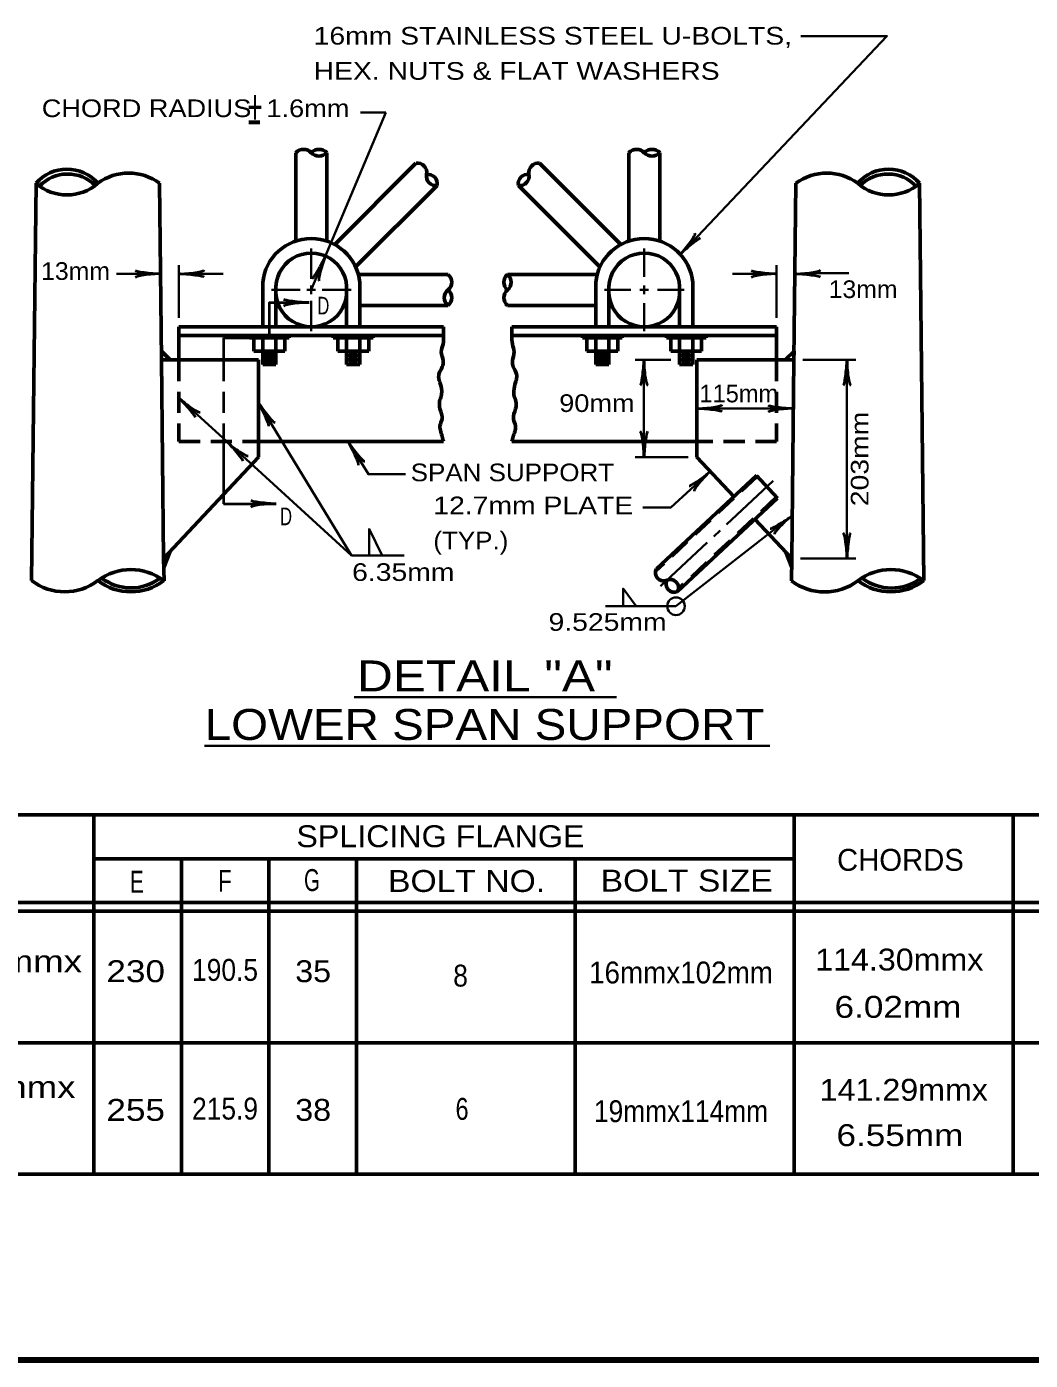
# Model space of a CAD drawing. Extents: x -29 to 827, y -14 to 530.
# Drawn here: x 320.1 to 457.6, y -2.8 to 179.9 of the extents above; entities that cross this region are included whole.
import ezdxf
from ezdxf.enums import TextEntityAlignment as Align

# ---------------------------------------------------------------- set-up
doc = ezdxf.new("R2010")
doc.units = 0
doc.header["$LTSCALE"] = 0.97
doc.linetypes.add('MEDIUM_DASHED', pattern=[4.5, 3, -1.5])
doc.layers.add('1', color=7, linetype='Continuous', lineweight=53)

msp = doc.modelspace()

# ---------------------------------------------------------------- linework, layer by layer
at = {"layer": '1', "lineweight": 35}
for p, q in [((359.0691, 143.7902), (369.2931, 168.1022)), ((369.2931, 168.1022), (365.8112, 168.1022)), ((359.0691, 149.4542), (359.0691, 145.3022)), ((404.7171, 149.4542), (404.7171, 145.5902)), ((340.9251, 139.9502), (340.9251, 147.1982)), ((422.8611, 139.9502), (422.8611, 147.1982)), ((338.4051, 145.9982), (332.3571, 145.9982)), ((340.9251, 145.9982), (346.9731, 145.9982)), ((359.0691, 144.3902), (359.0691, 143.1902)), ((404.7171, 144.3902), (404.7171, 143.1902)), ((422.8611, 145.9982), (416.8131, 145.9982)), ((426.7244, 146.0687), (432.7724, 146.0687)), ((353.6211, 143.7902), (357.5571, 143.7902)), ((360.5811, 143.7902), (364.5171, 143.7902)), ((402.8931, 143.7902), (399.2691, 143.7902)), ((405.3171, 143.7902), (404.1171, 143.7902)), ((410.1651, 143.7902), (406.5171, 143.7902)), ((359.0691, 142.2782), (359.0691, 138.1262)), ((404.7171, 141.9662), (404.7171, 138.1262)), ((408.3411, 134.2142), (403.4691, 134.2142)), ((404.6691, 134.2142), (404.6691, 120.8942)), ((426.4371, 134.2142), (433.7091, 134.2142)), ((432.4851, 134.2142), (432.4851, 106.9982)), ((340.9251, 129.0062), (347.4989, 123.0062)), ((364.5651, 107.4302), (351.8451, 128.3342)), ((411.9411, 127.5422), (425.1651, 127.5422)), ((347.4991, 123.0062), (364.5651, 107.4302)), ((410.7171, 120.8942), (403.4691, 120.8942)), ((422.4051, 117.6542), (415.9971, 111.6782)), ((409.0611, 100.4702), (424.9971, 112.8782)), ((415.1091, 110.8382), (414.2451, 110.0222)), ((413.3571, 109.2062), (406.9491, 103.2062)), ((364.5651, 107.4302), (371.8131, 107.4302)), ((426.1491, 106.9982), (433.7091, 106.9982)), ((409.0611, 100.4702), (399.3891, 100.4702)), ((364.9491, 87.9806), (400.9011, 87.9806)), ((344.4291, 81.3326), (421.9251, 81.3326))]:
    msp.add_line(p, q, dxfattribs=at)
at = {"layer": '1'}
for p, q in [((356.9571, 162.5822), (356.9571, 150.4862)), ((361.1811, 162.5822), (361.1811, 150.4862)), ((362.2851, 150.0062), (373.4211, 161.1662)), ((401.5011, 150.0062), (390.3411, 161.1662)), ((402.6051, 162.5822), (402.6051, 150.4862)), ((406.8291, 162.5822), (406.8291, 150.4862)), ((321.3411, 158.4062), (320.7411, 103.9742)), ((338.2851, 158.4062), (338.5491, 134.2142)), ((365.1411, 146.9342), (376.3251, 158.0942)), ((398.6211, 146.9342), (387.4611, 158.0942)), ((425.5011, 158.4062), (425.2371, 134.2142)), ((442.4451, 158.4062), (443.0451, 103.9742)), ((352.4211, 144.7982), (352.4211, 138.7502)), ((365.5251, 145.9022), (377.8131, 145.9022)), ((365.7171, 144.7982), (365.7171, 138.7502)), ((398.2611, 145.9022), (385.9731, 145.9022)), ((398.0691, 144.7982), (398.0691, 138.7502)), ((411.3651, 144.7982), (411.3651, 138.7502)), ((354.2211, 143.5742), (354.2211, 138.7502)), ((363.9171, 143.5742), (363.9171, 138.7502)), ((399.8691, 143.5742), (399.8691, 138.7502)), ((409.5411, 143.5742), (409.5411, 138.7502)), ((365.7171, 141.6782), (377.8131, 141.6782)), ((398.0691, 141.6782), (385.9731, 141.6782)), ((340.9251, 138.7502), (377.2131, 138.7502)), ((340.9251, 138.7502), (340.9251, 134.2142)), ((340.9251, 137.5262), (377.2131, 137.5262)), ((350.5971, 137.5262), (350.5971, 137.2382)), ((350.5971, 137.2382), (356.0451, 137.2382)), ((351.1971, 137.2382), (351.1971, 135.4142)), ((352.4211, 137.2382), (352.4211, 133.5902)), ((354.2211, 137.2382), (354.2211, 133.5902)), ((355.4451, 137.2382), (355.4451, 135.4142)), ((356.0451, 137.5262), (356.0451, 137.2382)), ((362.0931, 137.5262), (362.0931, 137.2382)), ((362.0931, 137.2382), (367.5411, 137.2382)), ((362.6931, 137.2382), (362.6931, 135.4142)), ((363.9171, 137.2382), (363.9171, 133.5902)), ((365.7171, 137.2382), (365.7171, 133.5902)), ((366.9411, 137.2382), (366.9411, 135.4142)), ((367.5411, 137.5262), (367.5411, 137.2382)), ((422.8611, 138.7502), (386.5731, 138.7502)), ((422.8611, 137.5262), (386.5731, 137.5262)), ((396.2451, 137.5262), (396.2451, 137.2382)), ((401.6931, 137.2382), (396.2451, 137.2382)), ((396.8451, 137.2382), (396.8451, 135.4142)), ((398.0691, 137.2382), (398.0691, 133.5902)), ((399.8691, 137.2382), (399.8691, 133.5902)), ((401.0931, 137.2382), (401.0931, 135.4142)), ((401.6931, 137.5262), (401.6931, 137.2382)), ((407.7411, 137.5262), (407.7411, 137.2382)), ((413.1891, 137.2382), (407.7411, 137.2382)), ((408.3411, 137.2382), (408.3411, 135.4142)), ((409.5411, 137.2382), (409.5411, 133.5902)), ((411.3651, 137.2382), (411.3651, 133.5902)), ((412.5651, 137.2382), (412.5651, 135.4142)), ((413.1891, 137.5262), (413.1891, 137.2382)), ((422.8611, 138.7502), (422.8611, 134.2142)), ((351.1971, 135.4142), (355.4451, 135.4142)), ((362.6931, 135.4142), (366.9411, 135.4142)), ((401.0931, 135.4142), (396.8451, 135.4142)), ((412.5651, 135.4142), (408.3411, 135.4142)), ((338.5491, 134.2142), (351.8451, 134.2142)), ((351.8451, 134.2142), (351.8451, 120.8942)), ((352.4211, 134.8142), (354.2211, 134.8142)), ((352.4211, 134.2142), (354.2211, 134.2142)), ((352.4211, 133.5902), (354.2211, 133.5902)), ((352.7091, 135.1022), (353.9331, 135.1022)), ((352.7091, 134.5022), (353.9331, 134.5022)), ((352.7091, 133.9022), (353.9331, 133.9022)), ((363.9171, 134.8142), (365.7171, 134.8142)), ((363.9171, 134.2142), (365.7171, 134.2142)), ((363.9171, 133.5902), (365.7171, 133.5902)), ((364.2051, 135.1022), (365.4291, 135.1022)), ((364.2051, 134.5022), (365.4291, 134.5022)), ((364.2051, 133.9022), (365.4291, 133.9022)), ((399.8691, 134.8142), (398.0691, 134.8142)), ((399.8691, 134.2142), (398.0691, 134.2142)), ((399.8691, 133.5902), (398.0691, 133.5902)), ((399.5811, 135.1022), (398.3571, 135.1022)), ((399.5811, 134.5022), (398.3571, 134.5022)), ((399.5811, 133.9022), (398.3571, 133.9022)), ((411.3651, 134.8142), (409.5411, 134.8142)), ((411.3651, 134.2142), (409.5411, 134.2142)), ((411.3651, 133.5902), (409.5411, 133.5902)), ((411.0531, 135.1022), (409.8531, 135.1022)), ((411.0531, 134.5022), (409.8531, 134.5022)), ((411.0531, 133.9022), (409.8531, 133.9022)), ((411.9411, 134.2142), (411.9411, 120.8942)), ((425.2371, 134.2142), (411.9411, 134.2142)), ((351.8451, 123.0062), (377.2131, 123.0062)), ((411.9411, 123.0062), (386.5731, 123.0062)), ((351.8451, 120.8942), (338.8371, 106.9982)), ((411.9411, 120.8942), (416.9811, 115.4942)), ((420.0771, 118.3742), (406.3731, 105.5822)), ((420.0771, 118.3742), (422.9811, 115.2782)), ((422.9811, 115.2782), (409.2771, 102.4862)), ((419.8851, 112.3982), (424.9251, 106.9982)), ((338.8371, 106.9982), (338.8851, 103.9502)), ((424.9251, 106.9982), (424.9011, 103.9502)), ((329.2642, 71.8697), (329.2642, 22.6697)), ((425.2642, 71.8697), (425.2642, 22.6697)), ((455.2642, 71.8697), (455.2642, 22.6697)), ((329.2642, 65.8697), (425.2642, 65.8697)), ((341.2642, 65.8697), (341.2642, 22.6697)), ((353.2642, 65.8697), (353.2642, 22.6697)), ((365.2642, 65.8697), (365.2642, 22.6697)), ((395.2642, 65.8697), (395.2642, 22.6697)), ((221.2642, 59.8697), (580.4623, 59.8697)), ((221.2642, 58.6697), (580.4623, 58.6697)), ((221.2642, 40.6697), (580.4623, 40.6697)), ((221.2642, 22.6697), (580.4623, 22.6697))]:
    msp.add_line(p, q, dxfattribs=at)
at = {"layer": '1', "lineweight": 40}
for p, q in [((347.0211, 137.2382), (347.0211, 134.2142)), ((347.0211, 123.0062), (347.0211, 114.5102)), ((347.0211, 114.5102), (354.2691, 114.5102))]:
    msp.add_line(p, q, dxfattribs=at)
at = {"layer": '1', "linetype": 'MEDIUM_DASHED', "lineweight": 40}
msp.add_line((347.0211, 134.2142), (347.0211, 123.0062), dxfattribs=at)
at = {"layer": '1', "linetype": 'MEDIUM_DASHED'}
for p, q in [((420.1731, 118.2782), (406.2771, 105.2702)), ((422.8611, 115.3982), (409.3971, 102.7982))]:
    msp.add_line(p, q, dxfattribs=at)
at = {"layer": '1', "lineweight": 158}
msp.add_line((820.0407, -2.8455), (28.4407, -2.8455), dxfattribs=at)
at = {"layer": '1', "lineweight": 35}
for points in [[(409.6611, 148.6622), (437.9736, 178.569), (426.1802, 178.569)], [(358.4691, 143.7902), (359.0691, 143.7902), (359.6691, 143.7902)], [(364.1331, 123.0062), (366.8931, 118.5422), (372.0051, 118.5422)], [(413.7651, 118.9262), (408.3411, 113.9822), (404.5251, 113.9822)], [(366.9891, 107.4302), (366.9891, 111.0542), (368.7891, 107.4302)], [(401.8131, 100.4702), (401.8131, 102.8702), (403.6131, 100.4702)]]:
    msp.add_lwpolyline(points, dxfattribs=at)
at = {"layer": '1', "lineweight": 40}
msp.add_lwpolyline([(347.0211, 137.2382), (353.3331, 137.2382), (353.3331, 142.0622), (358.7571, 142.0622)], dxfattribs=at)
at = {"layer": '1'}
for points in [[(338.5251, 135.4142), (339.7491, 134.2142), (338.5491, 134.2142)], [(425.2611, 135.4142), (424.0371, 134.2142), (425.2371, 134.2142)]]:
    msp.add_lwpolyline(points, close=True, dxfattribs=at)
for points in [[(338.5491, 134.2142), (338.8371, 106.9982), (339.6771, 107.8622), (338.8611, 105.7742), (338.8371, 106.9982)], [(425.2371, 134.2142), (424.9251, 106.9982), (424.1091, 107.8622), (424.9251, 105.7742), (424.9251, 106.9982)], [(221.2642, 71.8697), (329.2642, 71.8697), (425.2642, 71.8697), (580.4623, 71.8697)]]:
    msp.add_lwpolyline(points, dxfattribs=at)
at = {"layer": '1', "linetype": 'MEDIUM_DASHED'}
for points in [[(340.9251, 134.2142), (340.9251, 123.0062), (351.8451, 123.0062)], [(422.8611, 134.2142), (422.8611, 123.0062), (411.9411, 123.0062)]]:
    msp.add_lwpolyline(points, dxfattribs=at)
at = {"layer": '1', "lineweight": 35}
msp.add_circle((409.0627, 100.4608), 1.2096, dxfattribs=at)
at = {"layer": '1'}
for centre, radius, start, end in [((358.0087, 161.5878), 1.4582, 43.46312, 136.53688), ((360.1255, 161.5878), 1.4582, 43.46312, 136.53688), ((403.6554, 161.5878), 1.4582, 43.46312, 136.53688), ((405.7722, 161.5888), 1.4582, 43.46312, 136.53688), ((360.1255, 163.593), 1.4582, 223.46312, 316.53687), ((373.5949, 159.865), 1.3009, 349.34003, 97.33783), ((390.186, 159.865), 1.3009, 82.66217, 190.65997), ((405.7722, 163.594), 1.4582, 223.46312, 316.53687), ((325.5748, 154.759), 5.5813, 40.66498, 139.33502), ((325.682, 154.2875), 5.3757, 45.34412, 136.03167), ((334.042, 152.7314), 7.0719, 53.22658, 126.77342), ((376.1518, 159.3836), 1.3009, 169.34003, 277.33783), ((375.0395, 158.3342), 1.3009, 349.34003, 97.33783), ((388.7414, 158.3342), 1.3009, 82.66217, 190.65997), ((387.6291, 159.3836), 1.3009, 262.66217, 10.65997), ((429.7389, 152.7314), 7.0719, 53.22658, 126.77342), ((438.2061, 154.759), 5.5813, 40.66498, 139.33502), ((438.0989, 154.2875), 5.3757, 43.96833, 134.65588), ((325.5748, 163.2189), 6.4175, 228.72298, 311.27702), ((438.2061, 163.2189), 6.4175, 228.72298, 311.27702), ((359.0671, 144.1561), 6.6829, 5.43705, 174.56295), ((404.7138, 144.1561), 6.6829, 5.43705, 174.56295), ((359.0671, 143.9893), 4.8557, 355.16125, 184.83875), ((404.7138, 143.9893), 4.8557, 355.16125, 184.83875), ((376.9639, 144.8446), 1.3587, 308.8354, 51.1646), ((386.8154, 144.8446), 1.3587, 128.8354, 231.1646), ((385.1129, 144.8446), 1.3587, 308.8354, 51.1646), ((359.0671, 143.583), 4.8557, 175.16125, 4.83875), ((378.6664, 142.7278), 1.3587, 128.8354, 231.1646), ((376.9639, 142.7278), 1.3587, 308.8354, 51.1646), ((386.817, 142.7278), 1.3587, 128.8354, 231.1646), ((404.7138, 143.583), 4.8557, 175.16125, 4.83875), ((334.3444, 97.9986), 7.4811, 52.67567, 127.32434), ((334.3663, 109.6535), 6.6815, 232.97178, 306.38302), ((407.3634, 105.0468), 1.1159, 151.522, 294.60765), ((438.5081, 97.9984), 7.4811, 52.67567, 127.32434), ((438.6093, 109.6343), 6.6815, 232.97178, 306.38302), ((325.2724, 109.9131), 7.4811, 232.67566, 307.32433), ((334.3444, 109.9131), 7.4811, 232.67566, 307.32433), ((408.809, 103.5002), 1.1159, 151.522, 294.60765), ((408.2928, 103.0177), 1.1159, 331.522, 114.60765), ((429.4361, 109.8966), 7.4811, 232.67566, 307.32433), ((438.5081, 109.9129), 7.4811, 232.67566, 307.32433)]:
    msp.add_arc(centre, radius, start, end, dxfattribs=at)
at = {"layer": '1', "lineweight": 40}
for centre, major_axis, ratio, start_param, end_param in [((410.3169, 149.8469), (-1.3478, -1.6984), 0.122415, 0.89635335, 3.14159265), ((410.7698, 149.4669), (-1.6149, -1.3968), 0.07063, 3.14071475, 5.41810995), ((360.2596, 147.2844), (1.019, 1.8764), 0.07063, 3.14071475, 5.41810995), ((360.8174, 147.0884), (0.6627, 2.0645), 0.122415, 0.89635335, 3.14159265), ((337.0442, 146.2549), (2.1246, -0.2125), 0.07063, 3.14071475, 5.41810995), ((337.0442, 146.2549), (2.1246, -0.2125), 0.07063, 3.14071475, 5.41810995), ((342.243, 146.3331), (-2.16, -0.1889), 0.122415, 0.89635335, 3.14159265), ((342.243, 146.3331), (-2.16, -0.1889), 0.122415, 0.89635335, 3.14159265), ((421.5024, 146.2549), (2.1246, -0.2125), 0.07063, 3.14071475, 5.41810995), ((426.7012, 146.3331), (-2.16, -0.1889), 0.122415, 0.89635335, 3.14159265), ((337.0797, 145.6647), (2.16, 0.1889), 0.122415, 0.89635335, 3.14159265), ((337.0797, 145.6647), (2.16, 0.1889), 0.122415, 0.89635335, 3.14159265), ((342.2785, 145.743), (-2.1246, 0.2125), 0.07063, 3.14071475, 5.41810995), ((342.2785, 145.743), (-2.1246, 0.2125), 0.07063, 3.14071475, 5.41810995), ((421.5379, 145.6647), (2.16, 0.1889), 0.122415, 0.89635335, 3.14159265), ((426.7367, 145.743), (-2.1246, 0.2125), 0.07063, 3.14071475, 5.41810995), ((357.4094, 142.3237), (2.1246, -0.2125), 0.07063, 3.14071475, 5.41810995), ((357.4448, 141.7335), (2.16, 0.1889), 0.122415, 0.89635335, 3.14159265), ((404.4174, 132.8501), (0.2125, 2.1246), 0.07063, 3.14071475, 5.41810995), ((404.4174, 132.8501), (0.2125, 2.1246), 0.07063, 3.14071475, 5.41810995), ((405.0076, 132.8855), (-0.1889, 2.16), 0.122415, 0.89635335, 3.14159265), ((405.0076, 132.8855), (-0.1889, 2.16), 0.122415, 0.89635335, 3.14159265), ((432.2383, 132.8501), (0.2125, 2.1246), 0.07063, 3.14071475, 5.41810995), ((432.2383, 132.8501), (0.2125, 2.1246), 0.07063, 3.14071475, 5.41810995), ((432.8285, 132.8855), (-0.1889, 2.16), 0.122415, 0.89635335, 3.14159265), ((432.8285, 132.8855), (-0.1889, 2.16), 0.122415, 0.89635335, 3.14159265), ((341.7518, 127.9012), (1.4262, -1.5891), 0.07063, 6.28230741, 8.55970261), ((342.1234, 128.361), (-1.7228, 1.3164), 0.122415, 0.89635335, 3.14159265), ((352.3356, 127.0423), (0.9225, -1.9256), 0.07063, 6.28230741, 8.55970261), ((352.3356, 127.0423), (0.9225, -1.9256), 0.07063, 6.28230741, 8.55970261), ((352.8214, 127.3793), (-1.2838, 1.7473), 0.122415, 0.89635335, 3.14159265), ((352.8214, 127.3793), (-1.2838, 1.7473), 0.122415, 0.89635335, 3.14159265), ((413.2509, 127.8868), (-2.16, -0.1889), 0.122415, 0.89635335, 3.14159265), ((413.2509, 127.8868), (-2.16, -0.1889), 0.122415, 0.89635335, 3.14159265), ((423.8073, 127.8086), (2.1246, -0.2125), 0.07063, 3.14071475, 5.41810995), ((413.2863, 127.2967), (-2.1246, 0.2125), 0.07063, 3.14071475, 5.41810995), ((413.2863, 127.2967), (-2.1246, 0.2125), 0.07063, 3.14071475, 5.41810995), ((423.8428, 127.2184), (2.16, 0.1889), 0.122415, 0.89635335, 3.14159265), ((404.3392, 122.2197), (0.1889, -2.16), 0.122415, 0.89635335, 3.14159265), ((404.9293, 122.2552), (-0.2125, -2.1246), 0.07063, 3.14071475, 5.41810995), ((348.3211, 121.9122), (-1.4147, 1.5766), 0.07063, 3.14071475, 5.41810995), ((348.6898, 122.3684), (-1.7091, 1.3061), 0.122415, 0.89635335, 3.14159265), ((364.6271, 121.7104), (0.9383, -1.918), 0.07063, 6.28230741, 8.55970261), ((365.1101, 122.0513), (-1.2981, 1.7367), 0.122415, 0.89635335, 3.14159265), ((412.5918, 118.2119), (-1.7107, -1.2777), 0.07063, 6.28230741, 8.55970261), ((413.0164, 117.8005), (1.4659, 1.5976), 0.122415, 0.89635335, 3.14159265), ((352.9492, 114.1793), (2.16, 0.1889), 0.122415, 0.89635335, 3.14159265), ((352.9138, 114.7695), (2.1246, -0.2125), 0.07063, 3.14071475, 5.41810995), ((423.7729, 112.2434), (1.8067, 1.138), 0.07063, 3.14071475, 5.41810995), ((424.1636, 111.7996), (1.588, 1.4763), 0.122415, 0.89635335, 3.14159265), ((432.1601, 108.3075), (0.1889, -2.16), 0.122415, 0.89635335, 3.14159265), ((432.7502, 108.343), (-0.2125, -2.1246), 0.07063, 3.14071475, 5.41810995)]:
    msp.add_ellipse(centre, major_axis=major_axis, ratio=ratio, start_param=start_param, end_param=end_param, dxfattribs=at)
at = {"layer": '1'}
for points in [[(377.2131, 138.7502), (377.2131, 138.2702), (377.2131, 137.5262), (377.1411, 136.3742), (376.8771, 135.2942), (377.1411, 134.0702), (377.0211, 133.2542), (376.5651, 132.2462), (376.5651, 131.5502), (376.7091, 131.1182), (376.9491, 129.9662), (376.8771, 129.2462), (376.6611, 128.5502), (376.7091, 127.5182), (376.9971, 126.1022), (376.7091, 125.1662), (376.8291, 124.3502), (377.0211, 123.7262), (377.2131, 123.0062)], [(386.5731, 138.7502), (386.5491, 138.2702), (386.5731, 137.5262), (386.6451, 136.3742), (386.8851, 135.2942), (386.6451, 134.0702), (386.7651, 133.2542), (387.1971, 132.2462), (387.1971, 131.5502), (387.0771, 131.1182), (386.8371, 129.9662), (386.8851, 129.2462), (387.1251, 128.5502), (387.0771, 127.5182), (386.7891, 126.1022), (387.0771, 125.1662), (386.9571, 124.3502), (386.7651, 123.7262), (386.5731, 123.0062)]]:
    msp.add_spline(points, degree=3, dxfattribs=at)

# ---------------------------------------------------------------- texts
for s, height, width, p in [('16mm STAINLESS STEEL U-BOLTS,', 2.419, 1.2, (359.3952, 177.4008)), ('HEX. NUTS & FLAT WASHERS', 2.419, 1.2, (359.3952, 172.5816)), ('CHORD RADIUS  1.6mm', 2.419, 1.15, (322.1284, 167.4686)), ('+', 4.8, 0.55, (350.3364, 166.4852)), ('13mm', 2.419, 1.05, (322.0383, 145.1678)), ('13mm', 2.419, 1.05, (429.9923, 142.6814)), ('D', 2.419, 0.7, (359.9091, 140.4302)), ('90mm', 2.419, 1.15, (393.054, 127.0718)), ('SPAN SUPPORT', 2.419, 1.1, (372.7011, 117.5822)), ('12.7mm PLATE', 2.419, 1.2, (375.8019, 113.063)), ('D', 2.419, 0.7, (354.7971, 111.5582)), ('(TYP.)', 2.419, 1.1, (375.8019, 108.2438)), ('6.35mm', 2.419, 1.2, (364.6686, 103.9277)), ('9.525mm', 2.419, 1.2, (391.5921, 97.091)), ('SPLICING FLANGE', 3, 1.1, (357.0273, 67.4522)), ('E', 3, 0.7, (334.2309, 61.2242)), ('F', 3, 0.75, (346.3202, 61.3352)), ('G', 3, 0.7, (358.0768, 61.4461)), ('BOLT NO.', 3, 1.15, (369.5902, 61.3215)), ('BOLT SIZE', 3, 1.15, (398.736, 61.3744)), ('8', 3, 0.9, (378.5297, 48.3577)), ('6', 3, 0.8, (378.8471, 30.1026))]:
    msp.add_text(s, height=height, dxfattribs=dict(at, width=width)).set_placement(p)
for s, height, p in [('-', 4.8, (350.1862, 164.9132)), ('115mm', 2.419, (412.2799, 128.3918)), ('CHORDS', 3, (431.1358, 64.2148))]:
    msp.add_text(s, height=height, dxfattribs=at).set_placement(p)
at = {"layer": '1', "width": 1.2}
msp.add_text('203mm', height=2.419, rotation=90, dxfattribs=at).set_placement((435.4501, 114.1637))
at = {"layer": '1'}
for s, height, width, p in [('DETAIL "A"', 4.234, 1.2, (382.8571, 88.7966)), ('LOWER SPAN SUPPORT', 4.234, 1.15, (382.814, 82.1486)), ('6.35mmx203.2mmx', 3, 1.25, (305.624, 50.3133)), ('114.30mmx', 3, 1.1, (439.6696, 50.5557)), ('230', 3, 1.2, (335.0005, 48.9605)), ('190.5', 3, 0.9, (347.2518, 49.1381)), ('35', 3, 1.1, (359.3255, 48.9605)), ('16mmx102mm', 3, 0.95, (409.7514, 48.7829)), ('6.02mm', 3, 1.2, (439.492, 44.0765)), ('6.35mmx203.2mmx', 3, 1.25, (304.7362, 33.0861)), ('141.29mmx', 3, 1.1, (440.291, 32.7133)), ('255', 3, 1.2, (335.0005, 29.9605)), ('215.9', 3, 0.9, (347.2518, 30.1381)), ('38', 3, 1.1, (359.3255, 29.9605)), ('19mmx114mm', 3, 0.9, (409.7515, 29.7829)), ('6.55mm', 3, 1.2, (439.7583, 26.5005))]:
    msp.add_text(s, height=height, dxfattribs=dict(at, width=width)).set_placement(p, align=Align.CENTER)

doc.saveas('drawing.dxf')
